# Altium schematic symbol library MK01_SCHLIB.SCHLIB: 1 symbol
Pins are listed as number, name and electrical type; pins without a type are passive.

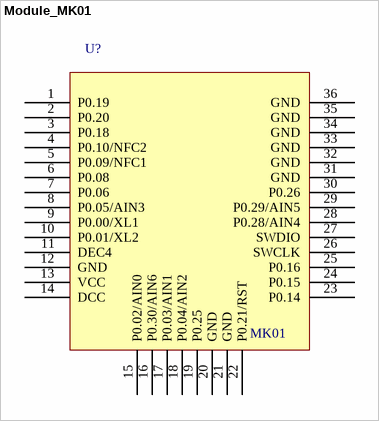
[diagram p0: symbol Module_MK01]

## Module_MK01
designator U?, comment MK01
footprint PCB_MK01 (Footprint not found)
pins: 1 P0.19, 2 P0.20, 3 P0.18, 4 P0.10/NFC2, 5 P0.09/NFC1, 6 P0.08, 7 P0.06, 8 P0.05/AIN3, 9 P0.00/XL1, 10 P0.01/XL2, 11 DEC4, 12 GND, 13 VCC, 14 DCC, 15 P0.02/AIN0, 16 P0.30/AIN6, 17 P0.03/AIN1, 18 P0.04/AIN2, 19 P0.25, 20 GND, 21 GND, 22 P0.21/RST, 23 P0.14, 24 P0.15, 25 P0.16, 26 SWCLK, 27 SWDIO, 28 P0.28/AIN4, 29 P0.29/AIN5, 30 P0.26, 31 GND, 32 GND, 33 GND, 34 GND, 35 GND, 36 GND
